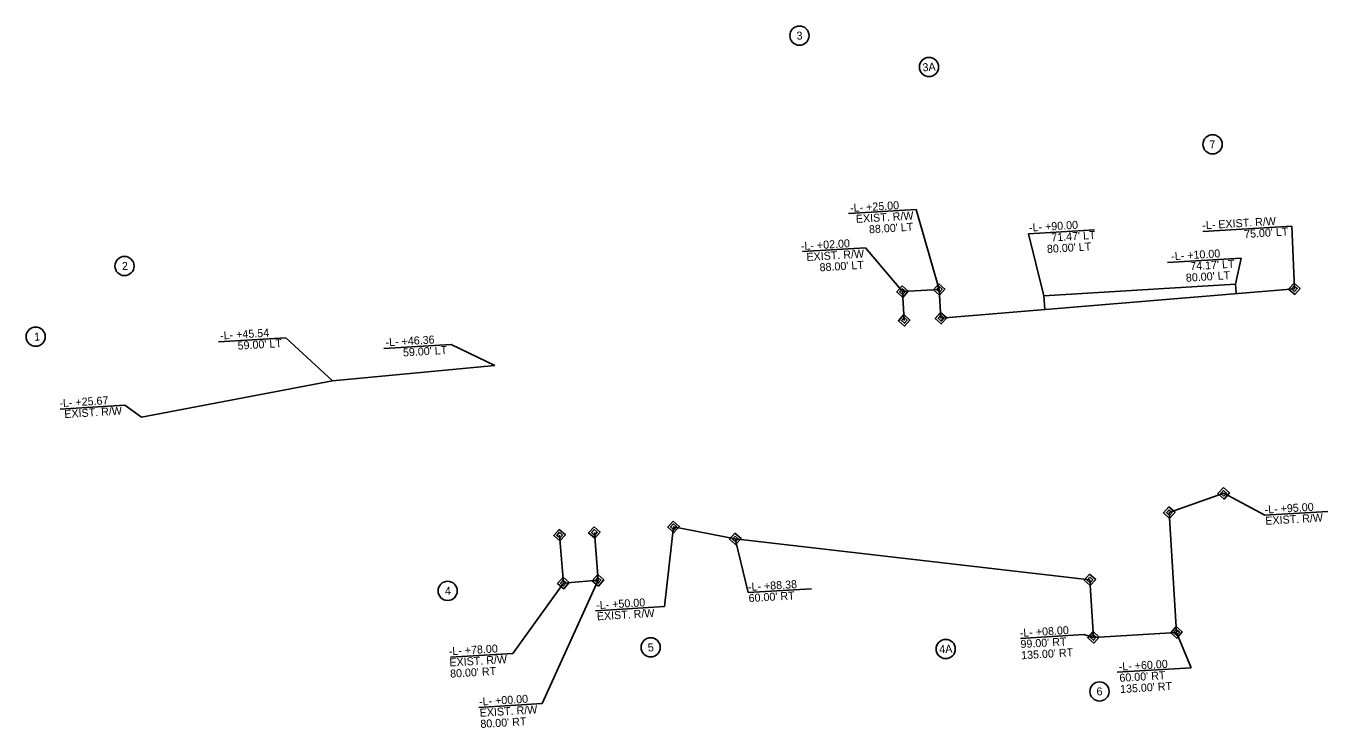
# Model space of a CAD drawing. Extents: x 2111158 to 2113189, y 670264 to 670757.
# Drawn here: x 2111158 to 2111971, y 670264 to 670703 of the extents above; entities that cross this region are included whole.
import ezdxf

# ---------------------------------------------------------------- set-up
doc = ezdxf.new("R2010")
doc.units = 0
for name, color, linetype in [('Exist Guardrail', 7, 'Continuous'), ('Exist Guardrail Text', 7, 'Continuous'), ('Exist Other Culture Anchor (Guy Wire) CELL', 7, 'Continuous'), ('Exist Other Culture Area Outline Leader', 7, 'Continuous'), ('Exist Other Culture Fence Line Text', 7, 'Continuous'), ('Exist Roads Soil', 7, 'Continuous'), ('Exist Structure Minor Footbridge', 7, 'Continuous'), ('Exist Utilities TV UG Cable SUE LOS B Cogo Number', 7, 'Continuous'), ('Exist Vegetation Woods Line', 7, 'Continuous'), ('Exist Vegetation Woods Line Text', 7, 'Continuous')]:
    doc.layers.add(name, color=color, linetype=linetype)

msp = doc.modelspace()

# ---------------------------------------------------------------- linework, layer by layer
at = {"layer": 'Exist Guardrail'}
for p, q in [((2111640.84, 670696.96), (2111640.84, 670696.96)), ((2111721.79, 670677.34), (2111721.79, 670677.34)), ((2111898.97, 670628.97), (2111898.97, 670628.97)), ((2111219.21, 670552.88), (2111219.21, 670552.88)), ((2111163.68, 670508.69), (2111163.68, 670508.69)), ((2111421.09, 670349.74), (2111421.09, 670349.74)), ((2111547.93, 670314.43), (2111547.93, 670314.43)), ((2111732.24, 670313.42), (2111732.24, 670313.42)), ((2111828.31, 670286.88), (2111828.31, 670286.88))]:
    msp.add_line(p, q, dxfattribs=at)
for centre in [(2111640.84, 670696.96), (2111721.79, 670677.34), (2111898.97, 670628.97), (2111219.21, 670552.88), (2111163.68, 670508.69), (2111421.09, 670349.74), (2111547.93, 670314.43), (2111732.24, 670313.42), (2111828.31, 670286.88)]:
    msp.add_circle(centre, 6, dxfattribs=at)
at = {"layer": 'Exist Guardrail Text'}
msp.add_line((2111729.27, 670520.29), (2111950.04, 670538.68), dxfattribs=at)
at = {"layer": 'Exist Other Culture Area Outline Leader'}
for p, q in [((2111793.54, 670534.2), (2111913.32, 670541.46)), ((2111913.32, 670541.46), (2111913.68, 670535.65)), ((2111794.06, 670525.69), (2111793.54, 670534.2)), ((2111349.06, 670481.04), (2111450.47, 670490.6)), ((2111229.85, 670458.43), (2111349.06, 670481.04))]:
    msp.add_line(p, q, dxfattribs=at)
at = {"layer": 'Exist Other Culture Fence Line Text'}
for p, q in [((2111705.22, 670536.87), (2111728.18, 670538.26)), ((2111706.31, 670518.9), (2111705.22, 670536.87)), ((2111729.27, 670520.29), (2111728.18, 670538.26)), ((2111493.4, 670354.67), (2111491.01, 670384.58)), ((2111515.02, 670356.36), (2111512.75, 670386.27)), ((2111493.4, 670354.67), (2111515.02, 670356.36))]:
    msp.add_line(p, q, dxfattribs=at)
at = {"layer": 'Exist Roads Soil'}
for p, q in [((2111784.04, 670573.05), (2111825.12, 670575.54)), ((2111793.54, 670534.2), (2111784.04, 670573.05)), ((2111870.84, 670555.03), (2111916.92, 670557.83)), ((2111913.32, 670541.46), (2111916.92, 670557.83)), ((2111277.98, 670505.51), (2111319.94, 670508.06)), ((2111319.94, 670508.06), (2111349.06, 670481.04)), ((2111381.26, 670501.25), (2111423.23, 670503.8)), ((2111423.23, 670503.8), (2111450.47, 670490.6)), ((2111179.02, 670463.34), (2111219.44, 670465.79)), ((2111219.44, 670465.79), (2111229.85, 670458.43))]:
    msp.add_line(p, q, dxfattribs=at)
at = {"layer": 'Exist Structure Minor Footbridge'}
for p, q in [((2111705.22, 670536.87), (2111705.22, 670536.87)), ((2111728.18, 670538.26), (2111728.18, 670538.26)), ((2111950.04, 670538.68), (2111950.04, 670538.68)), ((2111706.31, 670518.9), (2111706.31, 670518.9)), ((2111729.27, 670520.29), (2111729.27, 670520.29)), ((2111931.68, 670397.04), (2111905.91, 670410.77)), ((2111905.91, 670410.77), (2111905.91, 670410.77)), ((2111871.88, 670398.69), (2111871.88, 670398.69)), ((2111971.04, 670399.43), (2111931.68, 670397.04)), ((2111556.46, 670339.99), (2111562.19, 670389.82)), ((2111562.19, 670389.82), (2111562.19, 670389.82)), ((2111491.01, 670384.58), (2111491.01, 670384.58)), ((2111512.75, 670386.27), (2111512.75, 670386.27)), ((2111608.89, 670348.69), (2111600.76, 670382.26)), ((2111600.76, 670382.26), (2111600.76, 670382.26)), ((2111515.02, 670356.36), (2111480.11, 670279.25)), ((2111515.02, 670356.36), (2111515.02, 670356.36)), ((2111822.34, 670356.62), (2111822.34, 670356.62)), ((2111493.4, 670354.67), (2111461.74, 670310.67)), ((2111493.4, 670354.67), (2111493.4, 670354.67)), ((2111648.49, 670351.09), (2111608.89, 670348.69)), ((2111556.46, 670339.99), (2111513.41, 670337.38)), ((2111885.6, 670301.73), (2111876.42, 670323.83)), ((2111876.42, 670323.83), (2111876.42, 670323.83)), ((2111818.53, 670322.43), (2111778.93, 670320.03)), ((2111824.52, 670320.69), (2111818.53, 670322.43)), ((2111824.52, 670320.69), (2111824.52, 670320.69)), ((2111461.74, 670310.67), (2111422.81, 670308.31)), ((2111885.6, 670301.73), (2111839.28, 670298.92)), ((2111480.11, 670279.25), (2111440.51, 670276.85))]:
    msp.add_line(p, q, dxfattribs=at)
for points in [[(2111705, 670540.46), (2111708.81, 670537.08), (2111705.44, 670533.27), (2111701.63, 670536.65)], [(2111705.11, 670538.66), (2111707.02, 670536.97), (2111705.33, 670535.07), (2111703.42, 670536.76)], [(2111727.96, 670541.85), (2111731.77, 670538.47), (2111728.4, 670534.66), (2111724.58, 670538.04)], [(2111728.07, 670540.05), (2111729.97, 670538.37), (2111728.29, 670536.46), (2111726.38, 670538.15)], [(2111949.83, 670542.27), (2111953.64, 670538.89), (2111950.26, 670535.08), (2111946.45, 670538.46)], [(2111949.93, 670540.47), (2111951.84, 670538.79), (2111950.15, 670536.88), (2111948.25, 670538.57)], [(2111706.09, 670522.49), (2111709.9, 670519.12), (2111706.53, 670515.31), (2111702.72, 670518.68)], [(2111706.2, 670520.69), (2111708.11, 670519.01), (2111706.42, 670517.1), (2111704.51, 670518.79)], [(2111729.05, 670523.88), (2111732.86, 670520.51), (2111729.48, 670516.7), (2111725.67, 670520.07)], [(2111729.16, 670522.09), (2111731.06, 670520.4), (2111729.38, 670518.49), (2111727.47, 670520.18)], [(2111905.69, 670414.37), (2111909.5, 670410.99), (2111906.12, 670407.18), (2111902.31, 670410.56)], [(2111905.8, 670412.57), (2111907.7, 670410.88), (2111906.02, 670408.98), (2111904.11, 670410.67)], [(2111871.67, 670402.29), (2111875.48, 670398.91), (2111872.1, 670395.1), (2111868.29, 670398.48)], [(2111871.78, 670400.49), (2111873.68, 670398.8), (2111871.99, 670396.9), (2111870.09, 670398.59)], [(2111512.53, 670389.87), (2111516.34, 670386.49), (2111512.97, 670382.68), (2111509.16, 670386.05)], [(2111561.97, 670393.41), (2111565.78, 670390.03), (2111562.41, 670386.22), (2111558.59, 670389.6)], [(2111562.08, 670391.61), (2111563.98, 670389.92), (2111562.3, 670388.02), (2111560.39, 670389.71)], [(2111490.79, 670388.17), (2111494.6, 670384.79), (2111491.22, 670380.98), (2111487.41, 670384.36)], [(2111490.9, 670386.37), (2111492.8, 670384.69), (2111491.12, 670382.78), (2111489.21, 670384.47)], [(2111512.64, 670388.07), (2111514.55, 670386.38), (2111512.86, 670384.48), (2111510.95, 670386.16)], [(2111600.54, 670385.86), (2111604.35, 670382.48), (2111600.98, 670378.67), (2111597.17, 670382.04)], [(2111600.65, 670384.06), (2111602.56, 670382.37), (2111600.87, 670380.47), (2111598.96, 670382.15)], [(2111493.18, 670358.27), (2111496.99, 670354.89), (2111493.61, 670351.08), (2111489.8, 670354.45)], [(2111493.29, 670356.47), (2111495.19, 670354.78), (2111493.5, 670352.88), (2111491.6, 670354.56)], [(2111514.81, 670359.95), (2111518.62, 670356.58), (2111515.24, 670352.77), (2111511.43, 670356.14)], [(2111514.92, 670358.16), (2111516.82, 670356.47), (2111515.13, 670354.56), (2111513.23, 670356.25)], [(2111822.12, 670360.21), (2111825.93, 670356.84), (2111822.56, 670353.03), (2111818.75, 670356.4)], [(2111822.23, 670358.42), (2111824.14, 670356.73), (2111822.45, 670354.82), (2111820.54, 670356.51)], [(2111824.3, 670324.28), (2111828.11, 670320.9), (2111824.73, 670317.09), (2111820.92, 670320.47)], [(2111876.2, 670327.42), (2111880.01, 670324.05), (2111876.64, 670320.24), (2111872.83, 670323.61)], [(2111876.31, 670325.63), (2111878.22, 670323.94), (2111876.53, 670322.04), (2111874.62, 670323.72)], [(2111824.41, 670322.48), (2111826.31, 670320.79), (2111824.63, 670318.89), (2111822.72, 670320.58)]]:
    msp.add_lwpolyline(points, close=True, dxfattribs=at)
at = {"layer": 'Exist Utilities TV UG Cable SUE LOS B Cogo Number'}
for p in [(2111892.94, 670574.49), (2111950.04, 670538.68)]:
    msp.add_line(p, (2111948.48, 670577.85), dxfattribs=at)
at = {"layer": 'Exist Vegetation Woods Line'}
for p, q in [((2111671.58, 670585.65), (2111713.79, 670588.21)), ((2111728.18, 670538.26), (2111713.79, 670588.21)), ((2111642.81, 670561.94), (2111682.16, 670564.32)), ((2111682.16, 670564.32), (2111705.22, 670536.87))]:
    msp.add_line(p, q, dxfattribs=at)
at = {"layer": 'Exist Vegetation Woods Line Text'}
for p, q in [((2111871.88, 670398.69), (2111905.91, 670410.77)), ((2111876.42, 670323.83), (2111871.88, 670398.69)), ((2111562.19, 670389.82), (2111600.76, 670382.26)), ((2111600.76, 670382.26), (2111822.34, 670356.62)), ((2111822.34, 670356.62), (2111824.52, 670320.69)), ((2111824.52, 670320.69), (2111876.42, 670323.83))]:
    msp.add_line(p, q, dxfattribs=at)

# ---------------------------------------------------------------- texts
at = {"layer": 'Exist Other Culture Anchor (Guy Wire) CELL'}
for s, p in [('3', (2111639.21, 670694.36)), ('3A', (2111717.88, 670674.6)), ('7', (2111897.11, 670626.36)), ('2', (2111217.74, 670550.29)), ('1', (2111162.88, 670506.14)), ('4', (2111419.48, 670347.14)), ('5', (2111546.29, 670311.82)), ('4A', (2111728.34, 670310.68)), ('6', (2111826.58, 670284.27))]:
    msp.add_text(s, height=5, rotation=3.46824, dxfattribs=at).set_placement(p)
at = {"layer": 'Exist Roads Soil'}
for s, p in [('-L- +90.00', (2111784.41, 670574.39)), ("80.00' LT", (2111795.62, 670561.04)), ("71.47' LT", (2111798.34, 670568.22)), ('-L- +10.00', (2111873.25, 670556.5)), ("74.17' LT", (2111885.14, 670550.21)), ("80.00' LT", (2111882.42, 670543.03)), ('-L- +45.54', (2111279.07, 670506.9)), ("59.00' LT", (2111290.02, 670500.55)), ('-L- +46.36', (2111382.43, 670502.64)), ("59.00' LT", (2111393.3, 670496.29)), ('-L- +25.67', (2111178.64, 670464.63)), ('EXIST. R/W', (2111181.73, 670457.81))]:
    msp.add_text(s, height=5, rotation=3.46824, dxfattribs=at).set_placement(p)
at = {"layer": 'Exist Structure Minor Footbridge'}
for s, p in [('-L- +95.00', (2111931.62, 670398.04)), ('EXIST. R/W', (2111932.05, 670391.05)), ('-L- +88.38', (2111608.83, 670349.69)), ("60.00' RT", (2111609.25, 670342.7)), ('-L- +50.00', (2111514.01, 670338.31)), ('EXIST. R/W', (2111514.43, 670331.32)), ('-L- +08.00', (2111778.66, 670320.94)), ('-L- +78.00', (2111421.91, 670309.45)), ("99.00' RT", (2111779.09, 670313.95)), ('EXIST. R/W', (2111422.33, 670302.46)), ("135.00' RT", (2111779.51, 670306.96)), ("80.00' RT", (2111422.76, 670295.48)), ('-L- +60.00', (2111840.46, 670299.83)), ("60.00' RT", (2111840.89, 670292.84)), ("135.00' RT", (2111841.31, 670285.85)), ('-L- +00.00', (2111440.82, 670278)), ('EXIST. R/W', (2111441.25, 670271.01)), ("80.00' RT", (2111441.67, 670264.03))]:
    msp.add_text(s, height=5, rotation=3.46824, dxfattribs=at).set_placement(p)
at = {"layer": 'Exist Utilities TV UG Cable SUE LOS B Cogo Number'}
for s, p in [('-L- EXIST. R/W', (2111892.67, 670575.79)), ("75.00' LT", (2111918.79, 670570.36))]:
    msp.add_text(s, height=5, rotation=3.46824, dxfattribs=at).set_placement(p)
at = {"layer": 'Exist Vegetation Woods Line'}
for s, p in [('-L- +25.00', (2111672.61, 670586.64)), ('EXIST. R/W', (2111676.25, 670579.85)), ("88.00' LT", (2111684.45, 670573.34)), ('-L- +02.00', (2111641.9, 670562.83)), ('EXIST. R/W', (2111645.38, 670556.03)), ("88.00' LT", (2111653.59, 670549.52))]:
    msp.add_text(s, height=5, rotation=3.46824, dxfattribs=at).set_placement(p)

doc.saveas('drawing.dxf')
